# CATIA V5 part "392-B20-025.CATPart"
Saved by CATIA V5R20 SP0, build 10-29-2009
Part number: 392-B20-025
Definition: NONE
Nomenclature: 392-B20-025
Source: Unknown
Description: 392-B20-025
Bounding box of the stored display mesh (mm): x 0 to 25, y -9.278 to 9.278, z -9.2 to 9.2
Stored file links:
  C:\Users\Utente\Desktop\IO LAVORO\3D X SITO CF\X SITO\3D files 392B\392-B20-025.CATPart
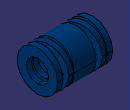
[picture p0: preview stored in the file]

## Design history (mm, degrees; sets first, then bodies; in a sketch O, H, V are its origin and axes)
Body1 "392-B20-025" (main body)
  Solid1: solid without history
